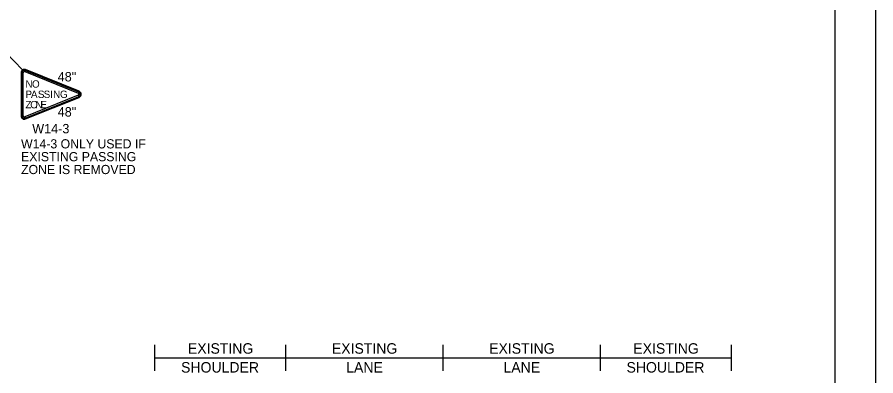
# Model space of a CAD drawing. Extents: x 99979.8 to 100075.7, y 99995 to 100010.7.
# Drawn here: x 100029.51 to 100036.06, y 100003.29 to 100006.03 of the extents above; entities that cross this region are included whole.
import ezdxf

# ---------------------------------------------------------------- set-up
doc = ezdxf.new("R2010")
doc.units = 0
for name, color, linetype in [('Default', 7, 'Continuous'), ('SH_GI_PlotLimits', 7, 'Continuous'), ('SH_GI_SheetBorder', 7, 'Continuous'), ('TR_SN_ConstructionSigns', 7, 'Continuous'), ('TR_WZ_WorkZoneDetails', 7, 'Continuous'), ('TR_WZ_WorkZoneTextCurrent', 7, 'Continuous')]:
    doc.layers.add(name, color=color, linetype=linetype)

msp = doc.modelspace()

# ---------------------------------------------------------------- linework, layer by layer
at = {"layer": 'Default'}
for p, q in [((100029.5695, 100005.6094), (100029.5732, 100005.6185)), ((100029.5732, 100005.6185), (100029.5695, 100005.6094)), ((100029.5695, 100005.6094), (100029.5732, 100005.6185)), ((100029.548, 100005.6015), (100029.5579, 100005.6015)), ((100029.5579, 100005.6015), (100029.548, 100005.6015)), ((100029.548, 100005.6015), (100029.548, 100005.6015)), ((100029.548, 100005.6015), (100029.5579, 100005.6015))]:
    msp.add_line(p, q, dxfattribs=at)
for radius in [0.0183, 0.0183, 0.00844, 0.00844]:
    msp.add_arc((100029.5663, 100005.6015), radius, 67.97569, 180.00001, dxfattribs=at)
at = {"layer": 'SH_GI_PlotLimits'}
msp.add_lwpolyline([(100019.0625, 99999.6875), (100036.0625, 99999.6875), (100036.0625, 100010.6875), (100019.0625, 100010.6875)], close=True, dxfattribs=at)
at = {"layer": 'SH_GI_SheetBorder'}
msp.add_line((100035.75, 100010.375), (100035.75, 100000), dxfattribs=at)
at = {"layer": 'TR_SN_ConstructionSigns'}
for p, q in [((100029.5732, 100005.6185), (100029.5695, 100005.6094)), ((100029.5695, 100005.6094), (100029.9773, 100005.4444)), ((100029.5695, 100005.6094), (100029.9773, 100005.4444)), ((100029.981, 100005.4535), (100029.5732, 100005.6185)), ((100029.981, 100005.4535), (100029.5732, 100005.6185)), ((100029.9836, 100005.46), (100029.5758, 100005.625)), ((100029.541, 100005.6015), (100029.541, 100005.2716)), ((100029.548, 100005.6015), (100029.548, 100005.2716)), ((100029.548, 100005.6015), (100029.548, 100005.2716)), ((100029.5579, 100005.6015), (100029.548, 100005.6015)), ((100029.5579, 100005.2716), (100029.5579, 100005.6015)), ((100029.5579, 100005.2716), (100029.5579, 100005.6015)), ((100029.9773, 100005.4288), (100029.5695, 100005.2638)), ((100029.9773, 100005.4288), (100029.5695, 100005.2638)), ((100029.5732, 100005.2547), (100029.981, 100005.4196)), ((100029.5732, 100005.2547), (100029.981, 100005.4196)), ((100029.5758, 100005.2482), (100029.9836, 100005.4131)), ((100029.981, 100005.4535), (100029.9773, 100005.4444)), ((100029.9773, 100005.4444), (100029.981, 100005.4535)), ((100029.981, 100005.4535), (100029.9773, 100005.4444)), ((100029.9773, 100005.4444), (100029.981, 100005.4535)), ((100029.9773, 100005.4288), (100029.981, 100005.4196)), ((100029.981, 100005.4196), (100029.9773, 100005.4288)), ((100029.9773, 100005.4288), (100029.981, 100005.4196)), ((100029.981, 100005.4196), (100029.9773, 100005.4288)), ((100029.981, 100005.4535), (100029.981, 100005.4535)), ((100029.5579, 100005.2716), (100029.548, 100005.2716)), ((100029.548, 100005.2716), (100029.5579, 100005.2716)), ((100029.5579, 100005.2716), (100029.548, 100005.2716)), ((100029.548, 100005.2716), (100029.5579, 100005.2716)), ((100029.5732, 100005.2547), (100029.5695, 100005.2638)), ((100029.5695, 100005.2638), (100029.5732, 100005.2547)), ((100029.5732, 100005.2547), (100029.5695, 100005.2638)), ((100029.5695, 100005.2638), (100029.5732, 100005.2547)), ((100029.5732, 100005.2547), (100029.5732, 100005.2547))]:
    msp.add_line(p, q, dxfattribs=at)
for centre, radius, start, end in [((100029.5663, 100005.6015), 0.0253, 67.97569, 180), ((100029.9741, 100005.4366), 0.00844, 292.02433, 67.97569), ((100029.9741, 100005.4366), 0.00844, 292.02433, 67.97569), ((100029.9741, 100005.4366), 0.0183, 292.02433, 67.97569), ((100029.9741, 100005.4366), 0.0183, 292.02433, 67.97569), ((100029.9741, 100005.4366), 0.0253, 292.02432, 67.9757), ((100029.5663, 100005.2716), 0.0253, 180, 292.02432), ((100029.5663, 100005.2716), 0.0183, 180.00001, 292.02433), ((100029.5663, 100005.2716), 0.0183, 180.00001, 292.02433), ((100029.5663, 100005.2716), 0.00844, 180.00001, 292.02433), ((100029.5663, 100005.2716), 0.00844, 180.00001, 292.02433)]:
    msp.add_arc(centre, radius, start, end, dxfattribs=at)
at = {"layer": 'TR_WZ_WorkZoneDetails'}
for p, q in [((100029.5522, 100005.6225), (100029.3425, 100005.8393)), ((100030.5621, 100003.3244), (100030.5621, 100003.5244)), ((100031.5621, 100003.3244), (100031.5621, 100003.5244)), ((100032.7621, 100003.3244), (100032.7621, 100003.5244)), ((100033.9621, 100003.3244), (100033.9621, 100003.5244)), ((100034.9621, 100003.3244), (100034.9621, 100003.5244)), ((100030.5621, 100003.4244), (100031.5621, 100003.4244)), ((100031.5621, 100003.4244), (100032.7621, 100003.4244)), ((100032.7621, 100003.4244), (100033.9621, 100003.4244)), ((100033.9621, 100003.4244), (100034.9621, 100003.4244))]:
    msp.add_line(p, q, dxfattribs=at)

# ---------------------------------------------------------------- texts
at = {"layer": 'TR_SN_ConstructionSigns'}
for s, height, p in [('48"', 0.072, (100029.8204, 100005.5347)), ('N', 0.0562, (100029.5744, 100005.4872)), ('O', 0.0562, (100029.6244, 100005.4872)), ('P', 0.0562, (100029.5744, 100005.4085)), ('A', 0.0562, (100029.6163, 100005.4085)), ('S', 0.0562, (100029.6691, 100005.4085)), ('S', 0.0562, (100029.7135, 100005.4085)), ('I', 0.0562, (100029.7622, 100005.4085)), ('N', 0.0562, (100029.786, 100005.4085)), ('G', 0.0562, (100029.8378, 100005.4085)), ('Z', 0.0562, (100029.5744, 100005.3297)), ('O', 0.0562, (100029.6108, 100005.3297)), ('N', 0.0562, (100029.6505, 100005.3297)), ('E', 0.0562, (100029.6891, 100005.3297))]:
    msp.add_text(s, height=height, dxfattribs=at).set_placement(p)
for s, p in [('48"', (100029.8204, 100005.2665)), ('W14-3', (100029.6261, 100005.1383))]:
    msp.add_text(s, height=0.072, rotation=360, dxfattribs=at).set_placement(p)
at = {"layer": 'TR_WZ_WorkZoneDetails'}
for s, p in [('EXISTING', (100030.8138, 100003.4564)), ('EXISTING', (100031.9123, 100003.4564)), ('EXISTING', (100033.1123, 100003.4564)), ('EXISTING', (100034.2123, 100003.4564)), ('SHOULDER', (100030.7619, 100003.3124)), ('LANE', (100032.0217, 100003.3124)), ('LANE', (100033.2217, 100003.3124)), ('SHOULDER', (100034.1604, 100003.3124))]:
    msp.add_text(s, height=0.08, rotation=360, dxfattribs=at).set_placement(p)
at = {"layer": 'TR_WZ_WorkZoneTextCurrent'}
for s, p in [('W14-3 ONLY USED IF ', (100029.541, 100005.0234)), ('EXISTING PASSING', (100029.541, 100004.9254)), ('ZONE IS REMOVED', (100029.541, 100004.8274))]:
    msp.add_text(s, height=0.07, rotation=360, dxfattribs=at).set_placement(p)

doc.saveas('drawing.dxf')
